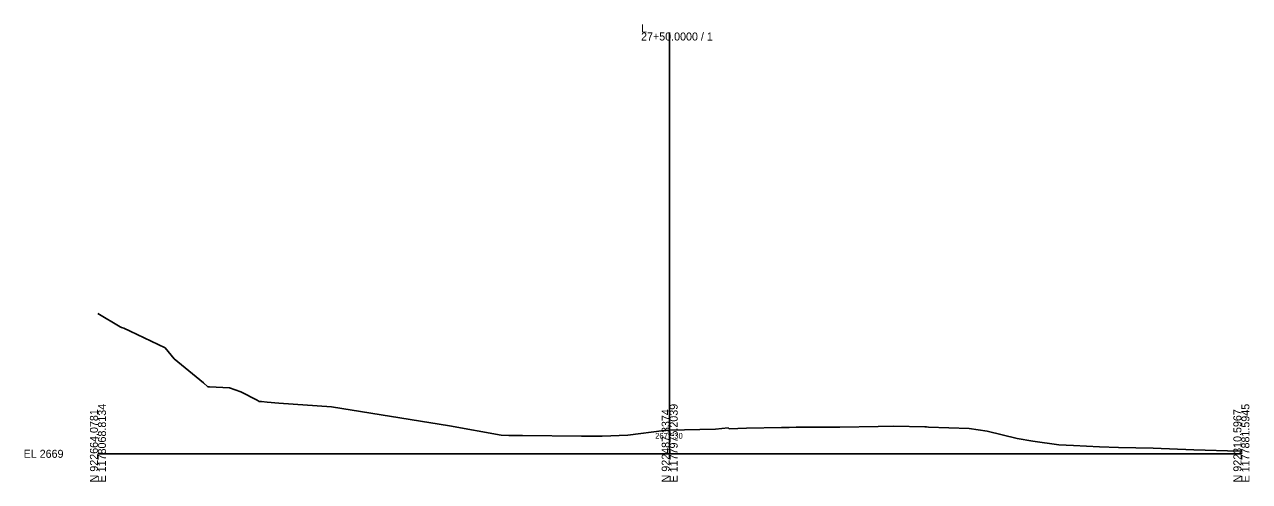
# Model space of a CAD drawing. Extents: x -26 to 1403, y -10 to 9563.
# Drawn here: x 974.3 to 1402.8, y 7490.3 to 7650.2 of the extents above; entities that cross this region are included whole.
import ezdxf

# ---------------------------------------------------------------- set-up
doc = ezdxf.new("R2010")
doc.units = 0
for name, color, linetype in [('Exist Cross Section Cell', 7, 'Continuous'), ('Exist XS Center Line Elevation Label', 7, 'Continuous'), ('Exist XS Ground Line', 7, 'Continuous')]:
    doc.layers.add(name, color=color, linetype=linetype)

msp = doc.modelspace()

# ---------------------------------------------------------------- linework, layer by layer
at = {"layer": 'Exist Cross Section Cell'}
for p, q in [((1200, 7500), (1200, 7647.43)), ((1000, 7500), (1200, 7500)), ((1200, 7500), (1400, 7500))]:
    msp.add_line(p, q, dxfattribs=at)
at = {"layer": 'Exist XS Ground Line'}
for p, q in [((1000, 7549.14), (1007.78, 7544.48)), ((1007.78, 7544.48), (1008.25, 7544.25)), ((1008.25, 7544.25), (1009.09, 7543.96)), ((1009.09, 7543.96), (1011.25, 7542.88)), ((1011.25, 7542.88), (1023.5, 7537.11)), ((1023.5, 7537.11), (1026.7, 7533.29)), ((1026.7, 7533.29), (1036.87, 7524.81)), ((1036.87, 7524.81), (1038.42, 7523.46)), ((1038.42, 7523.46), (1039.01, 7523.43)), ((1039.01, 7523.43), (1046.07, 7523.14)), ((1046.07, 7523.14), (1050, 7521.7)), ((1050, 7521.7), (1055.65, 7518.73)), ((1055.65, 7518.73), (1056.37, 7518.33)), ((1056.37, 7518.33), (1057.17, 7518.25)), ((1057.17, 7518.25), (1059.16, 7518.07)), ((1059.16, 7518.07), (1063.23, 7517.68)), ((1063.23, 7517.68), (1081.75, 7516.39)), ((1081.75, 7516.39), (1123.01, 7509.84)), ((1123.01, 7509.84), (1141.06, 7506.55)), ((1185.4, 7506.57), (1198.12, 7508.1)), ((1198.12, 7508.1), (1198.78, 7508.18)), ((1198.78, 7508.18), (1199.71, 7508.29)), ((1199.71, 7508.29), (1216.05, 7508.63)), ((1216.05, 7508.63), (1220.51, 7509.11)), ((1220.51, 7509.11), (1220.84, 7508.78)), ((1220.84, 7508.78), (1226.89, 7508.92)), ((1226.89, 7508.92), (1239.14, 7509.21)), ((1239.14, 7509.21), (1241.78, 7509.22)), ((1241.78, 7509.22), (1244.28, 7509.28)), ((1244.28, 7509.28), (1259.51, 7509.34)), ((1259.51, 7509.34), (1272.96, 7509.6)), ((1272.96, 7509.6), (1278.41, 7509.73)), ((1278.41, 7509.73), (1289.21, 7509.43)), ((1289.21, 7509.43), (1289.88, 7509.4)), ((1289.88, 7509.4), (1290.49, 7509.38)), ((1290.49, 7509.38), (1304.73, 7508.86)), ((1304.73, 7508.86), (1311.04, 7507.96)), ((1311.04, 7507.96), (1321.59, 7505.39)), ((1141.06, 7506.55), (1143.72, 7506.45)), ((1143.72, 7506.45), (1148.49, 7506.41)), ((1148.49, 7506.41), (1169.2, 7506.17)), ((1169.2, 7506.17), (1174.13, 7506.12)), ((1174.13, 7506.12), (1175.52, 7506.16)), ((1175.52, 7506.16), (1176.39, 7506.2)), ((1176.39, 7506.2), (1185.4, 7506.57)), ((1321.59, 7505.39), (1327.09, 7504.37)), ((1327.09, 7504.37), (1336.1, 7503.19)), ((1336.1, 7503.19), (1341.3, 7502.96)), ((1341.3, 7502.96), (1350.34, 7502.41)), ((1350.34, 7502.41), (1357.07, 7502.22)), ((1357.07, 7502.22), (1369.14, 7501.92)), ((1369.14, 7501.92), (1383.31, 7501.41)), ((1383.31, 7501.41), (1387.31, 7501.29)), ((1387.31, 7501.29), (1395.15, 7501.07)), ((1395.15, 7501.07), (1400, 7500.95))]:
    msp.add_line(p, q, dxfattribs=at)

# ---------------------------------------------------------------- texts
at = {"layer": 'Exist Cross Section Cell'}
for s, p in [('L', (1190, 7647.43)), ('27+50.0000 / 1', (1190, 7644.63)), ('EL 2669', (974, 7498.6))]:
    msp.add_text(s, height=2.8, dxfattribs=at).set_placement(p)
for s, p in [('E 1178068.8134', (1002.8, 7490)), ('E 1177975.2039', (1202.8, 7490)), ('E 1177881.5945', (1402.8, 7490)), ('N 922664.0781', (1000, 7490)), ('N 922487.3374', (1200, 7490)), ('N 922310.5967', (1400, 7490))]:
    msp.add_text(s, height=2.8, rotation=90, dxfattribs=at).set_placement(p)
at = {"layer": 'Exist XS Center Line Elevation Label'}
msp.add_text('2677.30', height=2, dxfattribs=at).set_placement((1194.92, 7505.3))

doc.saveas('drawing.dxf')
